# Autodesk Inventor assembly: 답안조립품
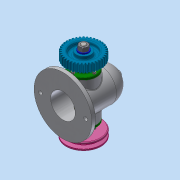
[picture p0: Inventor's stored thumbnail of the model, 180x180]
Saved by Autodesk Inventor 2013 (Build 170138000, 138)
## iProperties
Created: 2019-11
Part Number: 답안조립품
Document SubType Name: Assembly
Designer: Administrator
Author: Administrator
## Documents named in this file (14)
- C:\Users\Administrator\Desktop\491104V1055\답안조립품.iam
- C:\Users\Administrator\Desktop\491104V1055\본체.ipt
- C:\Users\Administrator\Desktop\491104V1055\V-벨트풀리.ipt
- V-벨트풀리.ipt
- C:\Users\Administrator\Desktop\491104V1055\너트 M12x1.25.ipt
- C:\Users\Administrator\Desktop\491104V1055\베어링 6203.ipt
- C:\Users\Administrator\Desktop\491104V1055\볼트 M4.ipt
- C:\Users\Administrator\Desktop\491104V1055\부시.ipt
- C:\Users\Administrator\Desktop\491104V1055\스퍼기어.ipt
- C:\Users\Administrator\Desktop\491104V1055\오일 실 26 38 8.ipt
- C:\Users\Administrator\Desktop\491104V1055\와셔 12x24.ipt
- C:\Users\Administrator\Desktop\491104V1055\축.ipt
- C:\Users\Administrator\Desktop\491104V1055\커버.ipt
- C:\Users\Administrator\Desktop\491104V1055\키 5x5x12.ipt
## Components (1 placed, 1 different names)
1. V-벨트풀리:1
